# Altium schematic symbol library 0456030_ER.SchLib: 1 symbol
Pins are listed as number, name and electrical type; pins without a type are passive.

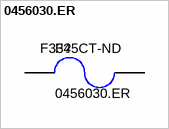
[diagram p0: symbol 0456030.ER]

## 0456030.ER
designator F?  Supplier Part Number: F3345CT-ND
FUSE BOARD MNT 30A 125VAC 72VDC; Manufacturer: Littelfuse Inc; U/M: EA; Fuse Type: Board Mount (Cartridge Style Excluded); DC Cold Resistance: 0.00132 Ohm; Breaking Capacity @ Rated Voltage: 100A AC, 500A DC; Response Time: Fast; Approvals: cULus, PSE; Voltage Rating - DC: 72V; Melting I²t: 81; Voltage Rating - AC: 125V
simulation model Fuse (Altium default FUSE subcircuit)
footprint 456 (LITTELFUSE 456 SERIES FUSE)
pins: 1, 2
